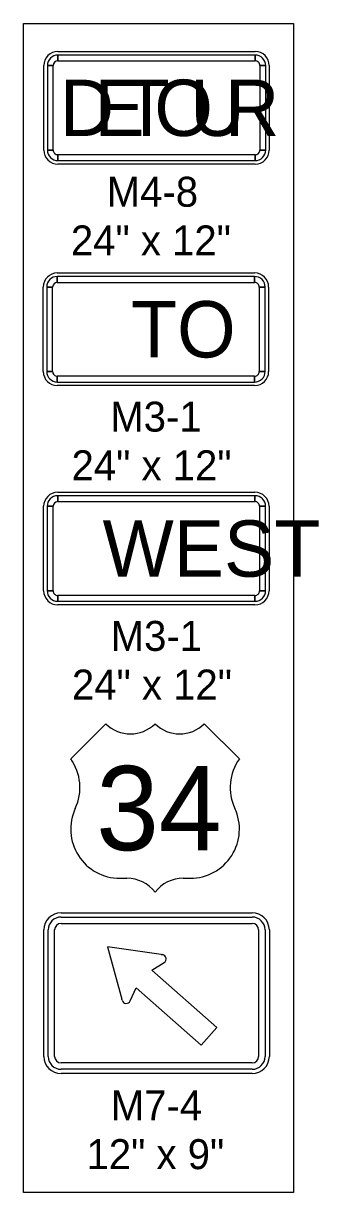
# Model space of a CAD drawing. Extents: x 10133 to 81668, y 6132 to 11018.
# Drawn here: x 11555.9 to 11634.7, y 6357.6 to 6669.8 of the extents above; entities that cross this region are included whole.
import ezdxf

# ---------------------------------------------------------------- set-up
doc = ezdxf.new("R2010")
doc.units = 0
for name, color, linetype in [('dsnTextFinalPlan', 7, 'Continuous'), ('Level 10', 7, 'Continuous'), ('Level 4', 7, 'Continuous'), ('Level 5', 7, 'Continuous')]:
    doc.layers.add(name, color=color, linetype=linetype)

msp = doc.modelspace()

# ---------------------------------------------------------------- linework, layer by layer
at = {"layer": 'dsnTextFinalPlan'}
for p, q in [((11565.97, 6432.34), (11616.94, 6432.34)), ((11561.39, 6393.97), (11561.39, 6427.76)), ((11621.52, 6427.76), (11621.52, 6393.97)), ((11616.94, 6389.39), (11565.97, 6389.39))]:
    msp.add_line(p, q, dxfattribs=at)
msp.add_lwpolyline([(11555.92, 6669.83), (11627.99, 6669.83), (11627.99, 6357.61), (11555.92, 6357.61)], close=True, dxfattribs=at)
for points in [[(11592.68, 6421.2), (11578.31, 6423.27), (11582.17, 6409.3)], [(11584.38, 6408.78), (11586.01, 6412.29), (11603.33, 6397.01), (11607.49, 6401.72), (11590.16, 6417), (11593.46, 6419.03)]]:
    msp.add_lwpolyline(points, dxfattribs=at)
for centre, radius, start, end in [((11565.97, 6427.76), 4.58, 90, 180), ((11616.94, 6427.76), 4.58, 0, 90), ((11609.21, 6535.98), 115.96, 261.8049, 261.9654), ((11592.84, 6420.01), 1.16, 302.6073, 81.9654), ((11470.39, 6378.44), 115.96, 15.2659, 15.4333), ((11583.36, 6409.27), 1.14, 195.2659, 334.5454), ((11565.97, 6393.97), 4.58, 180, 270), ((11616.94, 6393.97), 4.58, 270, 0)]:
    msp.add_arc(centre, radius, start, end, dxfattribs=at)
at = {"layer": 'Level 10'}
for p, q in [((11565.13, 6662.32), (11617.74, 6662.32)), ((11565.13, 6659.81), (11565.13, 6661.38)), ((11617.74, 6661.38), (11617.74, 6659.81)), ((11561.37, 6636.01), (11561.37, 6658.56)), ((11562.31, 6658.56), (11563.88, 6658.56)), ((11619, 6658.56), (11620.56, 6658.56)), ((11621.5, 6658.56), (11621.5, 6636.01)), ((11563.88, 6636.01), (11562.31, 6636.01)), ((11565.13, 6633.2), (11565.13, 6634.76)), ((11617.74, 6634.76), (11617.74, 6633.2)), ((11620.56, 6636.01), (11619, 6636.01)), ((11617.74, 6632.26), (11565.13, 6632.26)), ((11564.97, 6603.18), (11617.58, 6603.18)), ((11564.97, 6600.67), (11564.97, 6602.24)), ((11617.58, 6602.24), (11617.58, 6600.67)), ((11561.21, 6576.87), (11561.21, 6599.42)), ((11562.15, 6599.42), (11563.72, 6599.42)), ((11618.83, 6599.42), (11620.4, 6599.42)), ((11621.34, 6599.42), (11621.34, 6576.87)), ((11563.72, 6576.87), (11562.15, 6576.87)), ((11564.97, 6574.05), (11564.97, 6575.62)), ((11617.58, 6575.62), (11617.58, 6574.05)), ((11620.4, 6576.87), (11618.83, 6576.87)), ((11617.58, 6573.11), (11564.97, 6573.11)), ((11565.07, 6544.63), (11617.69, 6544.63)), ((11565.07, 6542.12), (11565.07, 6543.69)), ((11617.69, 6543.69), (11617.69, 6542.12)), ((11561.32, 6518.32), (11561.32, 6540.87)), ((11562.26, 6540.87), (11563.82, 6540.87)), ((11618.94, 6540.87), (11620.51, 6540.87)), ((11621.44, 6540.87), (11621.44, 6518.32)), ((11563.82, 6518.32), (11562.26, 6518.32)), ((11565.07, 6515.5), (11565.07, 6517.07)), ((11617.69, 6517.07), (11617.69, 6515.5)), ((11620.51, 6518.32), (11618.94, 6518.32)), ((11617.69, 6514.56), (11565.07, 6514.56)), ((11565.97, 6431.2), (11616.94, 6431.2)), ((11565.97, 6429.48), (11616.94, 6429.48)), ((11562.54, 6393.97), (11562.54, 6427.76)), ((11564.26, 6393.97), (11564.26, 6427.76)), ((11618.66, 6427.76), (11618.66, 6393.97)), ((11620.38, 6427.76), (11620.38, 6393.97)), ((11616.94, 6392.25), (11565.97, 6392.25)), ((11616.94, 6390.54), (11565.97, 6390.54))]:
    msp.add_line(p, q, dxfattribs=at)
for points in [[(11617.74, 6661.38), (11565.13, 6661.38), (11565.13, 6659.81), (11617.74, 6659.81), (11617.74, 6661.38)], [(11562.31, 6658.56), (11562.31, 6636.01), (11563.88, 6636.01), (11563.88, 6658.56), (11562.31, 6658.56)], [(11620.56, 6636.01), (11620.56, 6658.56), (11619, 6658.56), (11619, 6636.01), (11620.56, 6636.01)], [(11565.13, 6633.2), (11617.74, 6633.2), (11617.74, 6634.76), (11565.13, 6634.76), (11565.13, 6633.2)], [(11617.58, 6602.24), (11564.97, 6602.24), (11564.97, 6600.67), (11617.58, 6600.67), (11617.58, 6602.24)], [(11562.15, 6599.42), (11562.15, 6576.87), (11563.72, 6576.87), (11563.72, 6599.42), (11562.15, 6599.42)], [(11620.4, 6576.87), (11620.4, 6599.42), (11618.83, 6599.42), (11618.83, 6576.87), (11620.4, 6576.87)], [(11564.97, 6574.05), (11617.58, 6574.05), (11617.58, 6575.62), (11564.97, 6575.62), (11564.97, 6574.05)], [(11617.69, 6543.69), (11565.07, 6543.69), (11565.07, 6542.12), (11617.69, 6542.12), (11617.69, 6543.69)], [(11562.26, 6540.87), (11562.26, 6518.32), (11563.82, 6518.32), (11563.82, 6540.87), (11562.26, 6540.87)], [(11620.51, 6518.32), (11620.51, 6540.87), (11618.94, 6540.87), (11618.94, 6518.32), (11620.51, 6518.32)], [(11565.07, 6515.5), (11617.69, 6515.5), (11617.69, 6517.07), (11565.07, 6517.07), (11565.07, 6515.5)]]:
    msp.add_lwpolyline(points, close=True, dxfattribs=at)
for centre, radius, start, end in [((11565.13, 6658.56), 3.76, 90, 180), ((11565.13, 6658.56), 2.82, 90.0002, 179.9998), ((11565.13, 6658.56), 1.25, 90.0002, 179.9998), ((11617.74, 6658.56), 3.76, 0, 90), ((11617.74, 6658.56), 2.82, 0, 90.0002), ((11617.74, 6658.56), 1.25, 0, 90.0002), ((11565.13, 6636.01), 3.76, 180, 270), ((11565.13, 6636.01), 2.82, 179.9998, 270.0001), ((11565.13, 6636.01), 1.25, 179.9998, 270.0001), ((11617.74, 6636.01), 2.82, 270.0001, 0.0003), ((11617.74, 6636.01), 1.25, 270.0001, 0.0003), ((11617.74, 6636.01), 3.76, 270, 359.9911), ((11564.97, 6599.42), 3.76, 90, 180), ((11564.97, 6599.42), 2.82, 90.0002, 179.9998), ((11564.97, 6599.42), 1.25, 90.0002, 179.9998), ((11617.58, 6599.42), 3.76, 0, 90), ((11617.58, 6599.42), 2.82, 0, 90.0002), ((11617.58, 6599.42), 1.25, 0, 90.0002), ((11564.97, 6576.87), 3.76, 180, 270), ((11564.97, 6576.87), 2.82, 179.9998, 270.0001), ((11564.97, 6576.87), 1.25, 179.9998, 270.0001), ((11617.58, 6576.87), 2.82, 270.0001, 0.0003), ((11617.58, 6576.87), 1.25, 270.0001, 0.0003), ((11617.58, 6576.87), 3.76, 270, 359.9911), ((11565.07, 6540.87), 3.76, 90, 180), ((11617.69, 6540.87), 3.76, 0, 90), ((11565.07, 6540.87), 2.82, 90.0002, 179.9998), ((11565.07, 6540.87), 1.25, 90.0002, 179.9998), ((11617.69, 6540.87), 2.82, 0, 90.0002), ((11617.69, 6540.87), 1.25, 0, 90.0002), ((11565.07, 6518.32), 3.76, 180, 270), ((11565.07, 6518.32), 2.82, 179.9998, 270.0001), ((11565.07, 6518.32), 1.25, 179.9998, 270.0001), ((11617.69, 6518.32), 2.82, 270.0001, 0.0003), ((11617.69, 6518.32), 1.25, 270.0001, 0.0003), ((11617.69, 6518.32), 3.76, 270, 359.9911), ((11565.97, 6427.76), 3.44, 90, 180), ((11565.97, 6427.76), 1.72, 90, 180), ((11616.94, 6427.76), 3.44, 0, 90), ((11616.94, 6427.76), 1.72, 0, 90), ((11565.97, 6393.97), 3.44, 180, 270), ((11565.97, 6393.97), 1.72, 180, 270), ((11616.94, 6393.97), 3.44, 270, 0), ((11616.94, 6393.97), 1.72, 270, 0)]:
    msp.add_arc(centre, radius, start, end, dxfattribs=at)
at = {"layer": 'Level 4'}
for p, q in [((11577.91, 6482.79), (11568.53, 6473.42)), ((11613.53, 6473.42), (11604.16, 6482.79)), ((11581.66, 6441.54), (11583.53, 6441.54)), ((11598.53, 6441.54), (11600.41, 6441.54))]:
    msp.add_line(p, q, dxfattribs=at)
for centre, radius, start, end in [((11584.47, 6489.49), 9.38, 225.5729, 314.4272), ((11597.6, 6489.49), 9.38, 225.5729, 314.4272), ((11557.87, 6465.77), 13.13, 334.9895, 35.6629), ((11624.2, 6465.77), 13.13, 144.3372, 205.01), ((11581.66, 6454.67), 13.13, 154.9897, 270.0001), ((11600.41, 6454.67), 13.13, 270.0001, 25.0104), ((11583.53, 6432.17), 9.38, 36.8699, 90.0002), ((11598.53, 6432.17), 9.38, 90.0002, 143.13)]:
    msp.add_arc(centre, radius, start, end, dxfattribs=at)

# ---------------------------------------------------------------- texts
at = {"layer": 'Level 10'}
for s, height, p in [('D', 15.03, (11565.62, 6639.77)), ('E', 15.03, (11574.85, 6639.77)), ('T', 15.03, (11582.63, 6639.77)), ('O', 15.03, (11590.84, 6639.77)), ('U', 15.03, (11600.43, 6639.77)), ('R', 15.03, (11609.67, 6639.77)), ('TO', 15.032, (11584.63, 6580.63)), ('WEST', 15.032, (11577.05, 6522.08))]:
    msp.add_text(s, height=height, dxfattribs=at).set_placement(p)
at = {"layer": 'Level 4'}
msp.add_text('34', height=22.5, dxfattribs=at).set_placement((11575.33, 6449.04))
at = {"layer": 'Level 5'}
for s, p in [('M4-8', (11578.14, 6620.87)), ('24" x 12"', (11568.59, 6607.87)), ('M3-1', (11579.09, 6560.82)), ('24" x 12"', (11568.76, 6547.82)), ('M3-1', (11579.2, 6502.27)), ('24" x 12"', (11568.87, 6489.27)), ('M7-4', (11579.22, 6376.88)), ('12" x 9"', (11572.75, 6363.88))]:
    msp.add_text(s, height=8, dxfattribs=at).set_placement(p)

doc.saveas('drawing.dxf')
